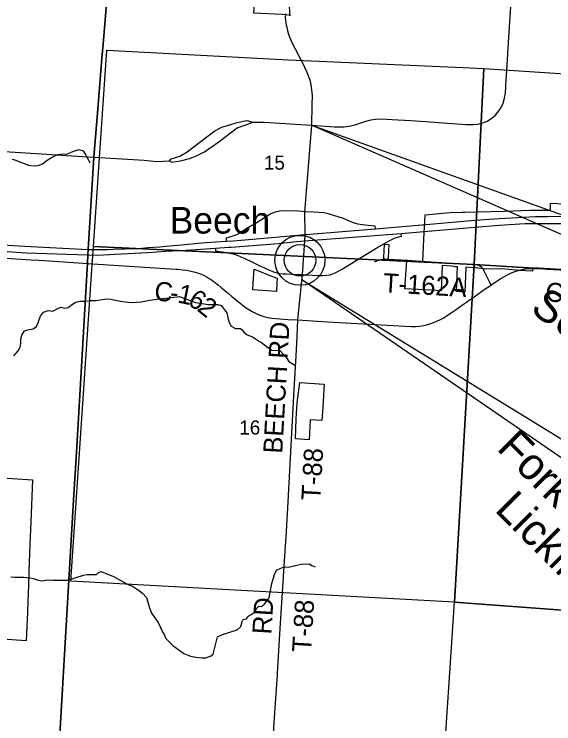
# Model space of a CAD drawing. Extents: x 0 to 91.3, y -0.7 to 22.
# Drawn here: x 4.519 to 6.125, y 16.113 to 18.226 of the extents above; entities that cross this region are included whole.
import ezdxf

# ---------------------------------------------------------------- set-up
doc = ezdxf.new("R2010")
doc.units = 0
for name, color, linetype in [('GM_X_City_Street', 7, 'Continuous'), ('GM_X_Corporation', 7, 'Continuous'), ('GM_X_County_Road', 7, 'Continuous'), ('GM_X_County_Road_Text', 7, 'Continuous'), ('GM_X_Interchange_Ramps', 7, 'Continuous'), ('GM_X_Major_River_Text', 7, 'Continuous'), ('GM_X_Minor_River', 7, 'Continuous'), ('GM_X_Section_Text', 7, 'Continuous'), ('GM_X_State_Route', 7, 'Continuous'), ('GM_X_Township_Road', 7, 'Continuous'), ('GM_X_Township_Road_Text', 7, 'Continuous'), ('GM_X_Unincorporated', 7, 'Continuous'), ('GM_X_Unincorporated_Location', 7, 'Continuous'), ('GM_X_Unincorporated_Text', 7, 'Continuous'), ('SH_Text', 7, 'Continuous')]:
    doc.layers.add(name, color=color, linetype=linetype)

msp = doc.modelspace()

# ---------------------------------------------------------------- linework, layer by layer
at = {"layer": 'GM_X_City_Street'}
for points in [[(5.9185, 17.9042), (5.9263, 17.9075), (5.938, 17.9144), (5.9511, 17.9248), (5.9617, 17.9381), (5.9681, 17.9482), (5.9742, 17.9604), (5.9787, 17.9752), (5.9809, 17.9914), (5.9831, 18.0298), (5.9839, 18.0432), (5.992, 18.1725), (5.9979, 18.2633)], [(4.9808, 17.7886), (4.9856, 17.7953), (5.0119, 17.8027), (5.0335, 17.8162), (5.0921, 17.8608), (5.1164, 17.8783), (5.1373, 17.8891), (5.1603, 17.8965), (5.1825, 17.9032), (5.2115, 17.9093), (5.2291, 17.9039)], [(4.9808, 17.7886), (4.9879, 17.7849), (5.0136, 17.7889), (5.0402, 17.796), (5.0614, 17.8044), (5.0857, 17.8162), (5.1279, 17.8459), (5.1582, 17.8695), (5.1825, 17.8877), (5.2082, 17.8965), (5.2291, 17.9039)], [(5.2291, 17.9039), (5.2621, 17.9046), (5.4038, 17.8952)], [(5.4038, 17.8952), (5.4726, 17.8905), (5.4854, 17.8899), (5.501, 17.8905), (5.5147, 17.8921), (5.5333, 17.8963), (5.5537, 17.9036), (5.5682, 17.9083), (5.5802, 17.9108), (5.5938, 17.913), (5.6108, 17.9139), (5.6434, 17.9119), (5.698, 17.9089), (5.7429, 17.9058), (5.863, 17.8977), (5.8764, 17.8972), (5.8856, 17.8969), (5.8987, 17.8986), (5.9137, 17.9022), (5.9185, 17.9042)], [(4.4901, 17.8172), (4.6159, 17.8088), (4.6734, 17.8048), (4.7564, 17.7996)], [(4.7564, 17.7996), (4.9058, 17.7906), (4.9431, 17.7872), (4.9808, 17.7886)]]:
    msp.add_lwpolyline(points, dxfattribs=at)
at = {"layer": 'GM_X_Corporation'}
for points in [[(4.8242, 18.6326), (4.7833, 18.1361), (4.7799, 18.0944), (4.7688, 17.9561), (4.7562, 17.8002), (4.7391, 17.5254), (4.7381, 17.5094), (4.7369, 17.4842), (4.7039, 16.921), (4.6966, 16.7952), (4.624, 15.5538), (4.6241, 15.5494), (4.6027, 15.2253), (4.5901, 15.0403), (4.5616, 14.5843), (4.5361, 14.2234), (4.5273, 14.1), (8.9, 14.1), (8.9, 20.9)], [(2.1, 20.8844), (2.1, 14.1), (4.5273, 14.1), (4.5361, 14.2234), (4.5616, 14.5843), (4.5901, 15.0403), (4.6027, 15.2253), (4.6241, 15.5494), (4.624, 15.5538), (4.6966, 16.7952), (4.7039, 16.921), (4.7369, 17.4842), (4.7381, 17.5094), (4.7391, 17.5254), (4.7562, 17.8002), (4.7688, 17.9561), (4.7799, 18.0944), (4.7833, 18.1361), (4.8242, 18.6326)], [(2.1, 20.8844), (2.1, 15.7138), (2.3611, 15.6969), (2.7426, 15.6727), (3.1007, 15.6507), (3.7652, 15.6088), (4.1118, 15.5861), (4.6241, 15.5494), (4.624, 15.5538), (4.6966, 16.7952), (4.7039, 16.921), (4.7369, 17.4842), (4.7381, 17.5094), (4.7391, 17.5254), (4.7562, 17.8002), (4.7688, 17.9561), (4.7799, 18.0944), (4.7833, 18.1361), (4.8242, 18.6326)], [(4.8242, 18.6326), (4.7833, 18.1361), (4.7799, 18.0944), (4.7688, 17.9561), (4.7562, 17.8002), (4.7391, 17.5254), (4.7381, 17.5094), (4.7369, 17.4842), (4.7039, 16.921), (4.6966, 16.7952), (4.624, 15.5538), (4.6241, 15.5494), (5.2553, 15.5081), (5.7371, 15.476), (6.438, 15.425), (7.1732, 15.3725), (7.6407, 15.3389), (8.8181, 15.2648), (8.9, 15.2596), (8.9, 20.4953)], [(6.2985, 17.4564), (6.0623, 17.4704), (6.0617, 17.461), (6.0219, 17.4626), (5.9813, 17.4666), (5.9641, 17.4672), (5.9208, 17.4665), (5.8935, 17.4705), (5.8883, 17.4707), (5.8631, 17.472), (5.86, 17.3984), (5.8349, 17.3997), (5.8387, 17.4733), (5.8318, 17.4731), (5.8217, 17.4756), (5.7931, 17.4774), (5.7895, 17.4023), (5.7613, 17.4038), (5.6812, 17.4083), (5.6871, 17.4923), (5.7349, 17.4894), (5.7386, 17.5558), (5.7424, 17.6284), (5.8168, 17.6356), (5.8529, 17.6365), (5.8603, 17.6367), (5.8979, 17.6376), (5.9785, 17.6393), (6.055, 17.6425), (6.1153, 17.6424), (6.115, 17.6633), (6.1545, 17.6609)], [(4.4516, 16.8473), (4.573, 16.8392), (4.5683, 16.7145), (4.5657, 16.647), (4.5627, 16.5665), (4.561, 16.5219), (4.5603, 16.5054), (4.558, 16.4455), (4.5546, 16.3598), (4.1706, 16.3862)]]:
    msp.add_lwpolyline(points, dxfattribs=at)
for points in [[(5.3367, 18.261), (5.3388, 18.2209), (5.3387, 18.2227), (5.316, 18.2244), (5.2323, 18.2289), (5.2343, 18.2618), (5.3284, 18.2562), (5.3292, 18.2694), (5.3367, 18.2689)], [(4.794, 18.1181), (5.3353, 18.0902), (5.8545, 18.0673), (5.9168, 18.0638), (5.8879, 17.4801), (4.755, 17.5344), (4.773, 17.7984)], [(5.9168, 18.0638), (6.3846, 18.0329), (6.9002, 17.9991), (6.9448, 17.9966), (6.9092, 17.4181), (5.8879, 17.4801)], [(5.6189, 17.5011), (5.6213, 17.5406), (5.6338, 17.5399), (5.6316, 17.5007), (5.6316, 17.5007), (5.6314, 17.4968), (5.6313, 17.4951), (5.6188, 17.4957)], [(4.755, 17.5344), (5.8879, 17.4801), (5.8298, 16.4755), (4.6878, 16.5376), (4.7073, 16.8304), (4.729, 17.1548), (4.7513, 17.4791)], [(5.8879, 17.4801), (6.9092, 17.4181), (6.8465, 16.3992), (5.8298, 16.4755)], [(5.2301, 17.4257), (5.2326, 17.4661), (5.3008, 17.4399), (5.3017, 17.4399), (5.3009, 17.4257), (5.2992, 17.4001), (5.2292, 17.405)], [(5.3579, 17.0205), (5.3615, 17.0682), (5.3694, 17.1289), (5.4413, 17.1244), (5.4374, 17.0554), (5.4343, 17.0159), (5.4, 17.0179), (5.3964, 16.9587), (5.3558, 16.9617)], [(5.8298, 16.4755), (6.8465, 16.3992), (6.7835, 15.4003), (6.727, 15.4038), (5.7634, 15.4732)]]:
    msp.add_lwpolyline(points, close=True, dxfattribs=at)
at = {"layer": 'GM_X_County_Road'}
for p, q in [((4.6804, 17.4873), (4.7371, 17.4837)), ((5.3616, 17.3152), (5.4517, 17.3101))]:
    msp.add_line(p, q, dxfattribs=at)
for points in [[(4.188, 17.5188), (4.2371, 17.5157), (4.5695, 17.4947), (4.592, 17.4929), (4.6804, 17.4873)], [(4.7371, 17.4837), (5, 17.4668), (5.0065, 17.4663), (5.0195, 17.465), (5.0325, 17.4633), (5.0452, 17.4608), (5.0578, 17.4576), (5.0701, 17.4534), (5.0821, 17.4483), (5.0936, 17.4423), (5.0992, 17.4388), (5.1047, 17.4354), (5.1154, 17.4277), (5.1256, 17.4197), (5.1357, 17.4113), (5.1458, 17.403), (5.1559, 17.3946), (5.166, 17.3863), (5.176, 17.3779), (5.186, 17.3697), (5.196, 17.3615), (5.2063, 17.3537), (5.2168, 17.3465), (5.2276, 17.3401), (5.2388, 17.3344), (5.2504, 17.3296), (5.2621, 17.3259), (5.274, 17.323), (5.2858, 17.3209), (5.2978, 17.3194), (5.3097, 17.3183), (5.3217, 17.3173), (5.3338, 17.3166), (5.3616, 17.3152)], [(5.4517, 17.3101), (5.7002, 17.296), (5.713, 17.2962), (5.7254, 17.2972), (5.7378, 17.299), (5.75, 17.3019), (5.7622, 17.3055), (5.7741, 17.3102), (5.786, 17.3157), (5.7975, 17.322), (5.8088, 17.3291), (5.8199, 17.3364), (5.8311, 17.3443), (5.8424, 17.3523), (5.8537, 17.3604), (5.865, 17.3684), (5.8764, 17.3764), (5.8877, 17.3843), (5.8989, 17.3921), (5.9102, 17.3999), (5.9212, 17.4076), (5.9323, 17.4151), (5.9379, 17.4189), (5.9658, 17.4375), (5.9887, 17.4507), (6.001, 17.4563), (6.0145, 17.4614), (6.0155, 17.4617)], [(6.0155, 17.4617), (6.0265, 17.4649), (6.0398, 17.4676), (6.0649, 17.4686)], [(6.0649, 17.4686), (6.0679, 17.4688), (6.0946, 17.4672)], [(6.0946, 17.4672), (6.1055, 17.4666), (6.1992, 17.4616), (6.3023, 17.4556)]]:
    msp.add_lwpolyline(points, dxfattribs=at)
at = {"layer": 'GM_X_Interchange_Ramps'}
for points in [[(5.3833, 17.6374), (5.3745, 17.6381), (5.3648, 17.639), (5.3333, 17.6405), (5.3098, 17.6389), (5.2959, 17.636), (5.2829, 17.6309), (5.2638, 17.6193), (5.2393, 17.6037), (5.2154, 17.5903), (5.1933, 17.5761), (5.1803, 17.5692), (5.1578, 17.5603), (5.1493, 17.5586), (5.1495, 17.5496)], [(5.4986, 17.6173), (5.4574, 17.6307), (5.4417, 17.6343), (5.4256, 17.6357), (5.4109, 17.636), (5.3866, 17.6372), (5.3833, 17.6374)], [(5.5943, 17.5864), (5.5933, 17.5949), (5.5627, 17.5971), (5.5418, 17.6005), (5.5259, 17.6059), (5.4986, 17.6173)], [(5.3761, 17.4507), (5.3883, 17.4499), (5.4229, 17.4472), (5.4372, 17.4473), (5.4493, 17.4484), (5.4587, 17.4497), (5.4703, 17.4537), (5.4931, 17.4651), (5.6013, 17.5318), (5.6351, 17.5512), (5.6531, 17.5597), (5.6714, 17.5647), (5.6709, 17.5722)], [(5.1178, 17.5288), (5.1182, 17.5206), (5.1503, 17.5166), (5.1596, 17.5145), (5.1699, 17.5119), (5.1808, 17.5087), (5.193, 17.5034), (5.203, 17.4995), (5.2117, 17.4954), (5.2217, 17.4904), (5.2317, 17.4855), (5.2418, 17.4806), (5.2518, 17.4758), (5.2619, 17.471), (5.2718, 17.4665), (5.2812, 17.4624), (5.2906, 17.4589), (5.3002, 17.4558), (5.3096, 17.4539), (5.3191, 17.4528), (5.3285, 17.4522), (5.3618, 17.4511), (5.3761, 17.4507)]]:
    msp.add_lwpolyline(points, dxfattribs=at)
at = {"layer": 'GM_X_Minor_River'}
for points in [[(4.5125, 17.7944), (4.5231, 17.7909), (4.5371, 17.7855), (4.5481, 17.7816), (4.5617, 17.7766), (4.578, 17.7739), (4.5898, 17.7753), (4.6031, 17.7806), (4.6165, 17.7907), (4.6302, 17.7986), (4.6397, 17.8039), (4.65, 17.808), (4.6625, 17.8098), (4.6754, 17.809), (4.6887, 17.8146), (4.699, 17.8191), (4.7116, 17.8232), (4.7241, 17.8189), (4.7323, 17.8056), (4.7376, 17.7953)], [(4.7376, 17.7953), (4.7439, 17.7831)], [(4.518, 17.2084), (4.531, 17.2235), (4.5367, 17.2341), (4.5387, 17.2458), (4.5388, 17.2595), (4.5411, 17.2697), (4.5492, 17.2826), (4.559, 17.2859), (4.5754, 17.2892), (4.5853, 17.2956), (4.5903, 17.3066), (4.593, 17.3169), (4.5973, 17.3267), (4.6061, 17.3384), (4.6201, 17.3433), (4.6342, 17.3413), (4.6483, 17.3495), (4.6578, 17.3537), (4.6695, 17.3506), (4.679, 17.3528), (4.6889, 17.3599), (4.7019, 17.3682), (4.714, 17.3708), (4.7304, 17.371)], [(4.7304, 17.371), (4.7446, 17.3733), (4.7613, 17.3732), (4.7947, 17.378), (4.8049, 17.3775), (4.8405, 17.3705), (4.869, 17.3673), (4.8963, 17.3691), (4.9214, 17.3743), (4.9597, 17.3787), (5.0106, 17.3852), (5.0587, 17.3675), (5.0727, 17.3648), (5.0959, 17.3613), (5.1247, 17.3608), (5.1349, 17.3581), (5.1515, 17.3363), (5.156, 17.3181), (5.1575, 17.312), (5.1593, 17.3055), (5.1646, 17.2972), (5.1774, 17.2899), (5.1922, 17.2898), (5.1975, 17.2856), (5.2021, 17.2788), (5.2123, 17.2707), (5.2285, 17.2653), (5.2493, 17.2516), (5.2543, 17.2493), (5.2701, 17.2359), (5.286, 17.2252), (5.3099, 17.2239), (5.3295, 17.2026), (5.3367, 17.1915), (5.356, 17.1801)], [(4.6787, 16.5408), (4.725, 16.5552), (4.7364, 16.5575), (4.7633, 16.5577), (4.7687, 16.5626), (4.7774, 16.566), (4.796, 16.5587), (4.8122, 16.5529), (4.858, 16.5276), (4.8705, 16.523), (4.8921, 16.5092), (4.9004, 16.502), (4.9125, 16.489), (4.9203, 16.4609), (4.9274, 16.4422), (4.9477, 16.4148), (4.9612, 16.3851), (4.965, 16.379), (4.9706, 16.3672), (4.9914, 16.3459), (5.0235, 16.3222), (5.0432, 16.3145), (5.0595, 16.3117), (5.0784, 16.3094), (5.0891, 16.3097), (5.1054, 16.3157), (5.1111, 16.3206), (5.1239, 16.3714), (5.1388, 16.3785), (5.1825, 16.3928), (5.1932, 16.4026), (5.197, 16.4177), (5.2001, 16.423), (5.21, 16.4249), (5.2138, 16.4321), (5.2199, 16.4362), (5.2264, 16.4396), (5.2363, 16.4475), (5.2401, 16.4566), (5.2474, 16.4634), (5.2538, 16.4623), (5.2629, 16.4679), (5.2775, 16.4883), (5.2853, 16.5308), (5.2934, 16.5574), (5.2973, 16.5668), (5.3015, 16.5717), (5.319, 16.5796), (5.3254, 16.5807), (5.3349, 16.5796), (5.3638, 16.5862), (5.3729, 16.5885), (5.3972, 16.5895), (5.4044, 16.5841), (5.4142, 16.5799)], [(4.5089, 16.5503), (4.5211, 16.5494), (4.5465, 16.5493), (4.556, 16.5481), (4.5654, 16.5477), (4.5764, 16.5453), (4.5897, 16.5407), (4.6018, 16.5387), (4.6121, 16.5409), (4.6246, 16.5412), (4.6349, 16.5408), (4.6485, 16.5403), (4.6787, 16.5408)]]:
    msp.add_lwpolyline(points, dxfattribs=at)
at = {"layer": 'GM_X_State_Route'}
msp.add_line((5.1178, 17.5288), (5.1579, 17.5315), dxfattribs=at)
for points in [[(5.5943, 17.5864), (5.7563, 17.6003), (5.8002, 17.604), (5.8904, 17.6119), (5.9627, 17.6172), (5.9805, 17.6185), (6.0166, 17.6205), (6.0705, 17.6229), (6.1063, 17.6237), (6.1423, 17.624), (6.2325, 17.6227), (6.3777, 17.6201), (6.4147, 17.6193)], [(5.7505, 17.5792), (5.8898, 17.5913), (5.9624, 17.5978), (6.0395, 17.6027), (6.0985, 17.6026), (6.2731, 17.602), (6.3364, 17.6018), (6.4089, 17.6), (6.4159, 17.5998)], [(5.1495, 17.5496), (5.1706, 17.5512), (5.2964, 17.5622), (5.3841, 17.5696), (5.3866, 17.5698), (5.4227, 17.5724), (5.46, 17.5753), (5.4957, 17.5784), (5.5943, 17.5864)], [(5.3589, 17.5484), (5.3828, 17.5509), (5.6709, 17.5722), (5.7505, 17.5792)], [(4.3709, 17.5457), (4.549, 17.5351), (4.7393, 17.5249)], [(4.7393, 17.5249), (4.7448, 17.5248), (4.7646, 17.5249), (4.7776, 17.5251), (4.7965, 17.5246), (4.8122, 17.5257), (4.8456, 17.5267), (4.8807, 17.5285), (4.8984, 17.5294), (4.9163, 17.5307), (4.9343, 17.532), (4.9524, 17.5334), (4.9703, 17.5351), (5.0063, 17.5382), (5.0879, 17.5456), (5.1495, 17.5496)], [(5.1579, 17.5315), (5.1649, 17.5319), (5.3043, 17.5427), (5.3589, 17.5484)], [(4.3685, 17.528), (4.5543, 17.5156), (4.7383, 17.5089)], [(4.7383, 17.5089), (4.7663, 17.5079), (4.8179, 17.5108), (4.9162, 17.5165), (4.9703, 17.5197), (5.0302, 17.5231), (5.1178, 17.5288)]]:
    msp.add_lwpolyline(points, dxfattribs=at)
at = {"layer": 'GM_X_Township_Road'}
for p, q in [((5.4038, 17.8952), (5.3833, 17.6374)), ((5.374, 17.4313), (5.3616, 17.3152)), ((5.3761, 17.4507), (5.374, 17.4313)), ((5.3616, 17.3152), (5.3596, 17.2655)), ((5.332, 16.7563), (5.3281, 16.6864))]:
    msp.add_line(p, q, dxfattribs=at)
for points in [[(5.3266, 18.2269), (5.3257, 18.2149), (5.3287, 18.1931), (5.3299, 18.1879)], [(5.3299, 18.1879), (5.3304, 18.1859), (5.3345, 18.1683), (5.3382, 18.158), (5.3399, 18.1533), (5.3461, 18.1391), (5.3638, 18.1054), (5.3685, 18.0965)], [(5.3685, 18.0965), (5.3769, 18.0805), (5.389, 18.055), (5.3932, 18.0455), (5.3989, 18.0295), (5.4022, 18.0159), (5.4053, 17.9838), (5.4048, 17.9552), (5.4038, 17.8952)], [(5.3833, 17.6374), (5.3841, 17.5696), (5.3828, 17.5509), (5.3761, 17.4507)], [(5.5911, 17.488), (5.6057, 17.4947), (5.6099, 17.495), (5.6196, 17.4968)], [(5.6196, 17.4968), (5.6216, 17.4972), (5.6296, 17.4966)], [(5.6296, 17.4966), (5.6316, 17.4965), (5.6899, 17.4928)], [(5.6899, 17.4928), (5.7281, 17.4904), (5.7301, 17.4903)], [(5.7301, 17.4903), (5.8665, 17.4816), (5.8974, 17.4796)], [(5.8974, 17.4796), (5.8984, 17.4795), (5.9076, 17.4747), (5.9132, 17.4682), (5.9157, 17.4644)], [(5.9157, 17.4644), (5.9162, 17.4637), (5.9331, 17.4296), (5.9379, 17.4189)], [(5.3596, 17.2655), (5.3573, 17.2087), (5.3535, 17.1409), (5.3526, 17.1259), (5.332, 16.7563)], [(5.3281, 16.6864), (5.328, 16.6844), (5.3244, 16.6266), (5.3225, 16.5967), (5.3088, 16.3806), (5.3019, 16.2634), (5.3016, 16.2584), (5.2917, 16.1165), (5.2558, 15.51)]]:
    msp.add_lwpolyline(points, dxfattribs=at)
at = {"layer": 'GM_X_Unincorporated'}
for radius in [0.0744, 0.0472]:
    msp.add_circle((5.3694, 17.4928), radius, dxfattribs=at)
at = {"layer": 'GM_X_Unincorporated_Location'}
msp.add_line((5.3694, 17.4928), (5.3694, 17.4928), dxfattribs=at)
at = {"layer": 'SH_Text'}
for points in [[(9.2012, 16.2343), (5.4038, 17.8952), (9.2012, 16.5366)], [(9.2012, 14.8079), (5.3743, 17.4358), (9.2012, 15.0876)]]:
    msp.add_lwpolyline(points, close=True, dxfattribs=at)

# ---------------------------------------------------------------- texts
at = {"layer": 'GM_X_County_Road_Text'}
for s, height, rotation, p in [('C', 0.0568, 355.4875, (4.9345, 17.3733)), ('1', 0.0568, 348.3033, (5.0024, 17.3677)), ('C-162', 0.05682, 356.1504, (6.0986, 17.3708)), ('-', 0.0568, 354.6296, (4.9808, 17.3696)), ('6', 0.0568, 328.3267, (5.0319, 17.3625)), ('2', 0.0568, 320.946, (5.0601, 17.3452))]:
    msp.add_text(s, height=height, rotation=rotation, dxfattribs=at).set_placement(p)
at = {"layer": 'GM_X_Major_River_Text'}
for s, height, rotation, p in [('South', 0.0947, 324.9987, (6.0514, 17.3406)), ('Fork', 0.0947, 314.9954, (5.9522, 16.9307)), ('Licking', 0.09471, 314.9945, (5.9464, 16.7478))]:
    msp.add_text(s, height=height, rotation=rotation, dxfattribs=at).set_placement(p)
at = {"layer": 'GM_X_Section_Text'}
for s, p in [('15', (5.2622, 17.7627)), ('16', (5.1889, 16.9742))]:
    msp.add_text(s, height=0.04186, rotation=0, dxfattribs=at).set_placement(p)
at = {"layer": 'GM_X_Township_Road_Text'}
for s, rotation, p in [('T-162A', 356.5838, (5.6154, 17.3981)), ('BEECH RD', 86.7889, (5.3166, 16.9163)), ('T-88', 86.8113, (5.4299, 16.7764)), ('RD', 86.5467, (5.2841, 16.378)), ('T-88', 86.4669, (5.4023, 16.3248))]:
    msp.add_text(s, height=0.05682, rotation=rotation, dxfattribs=at).set_placement(p)
at = {"layer": 'GM_X_Unincorporated_Text'}
msp.add_text('Beech', height=0.07898, rotation=0, dxfattribs=at).set_placement((4.9814, 17.5725))

doc.saveas('drawing.dxf')
